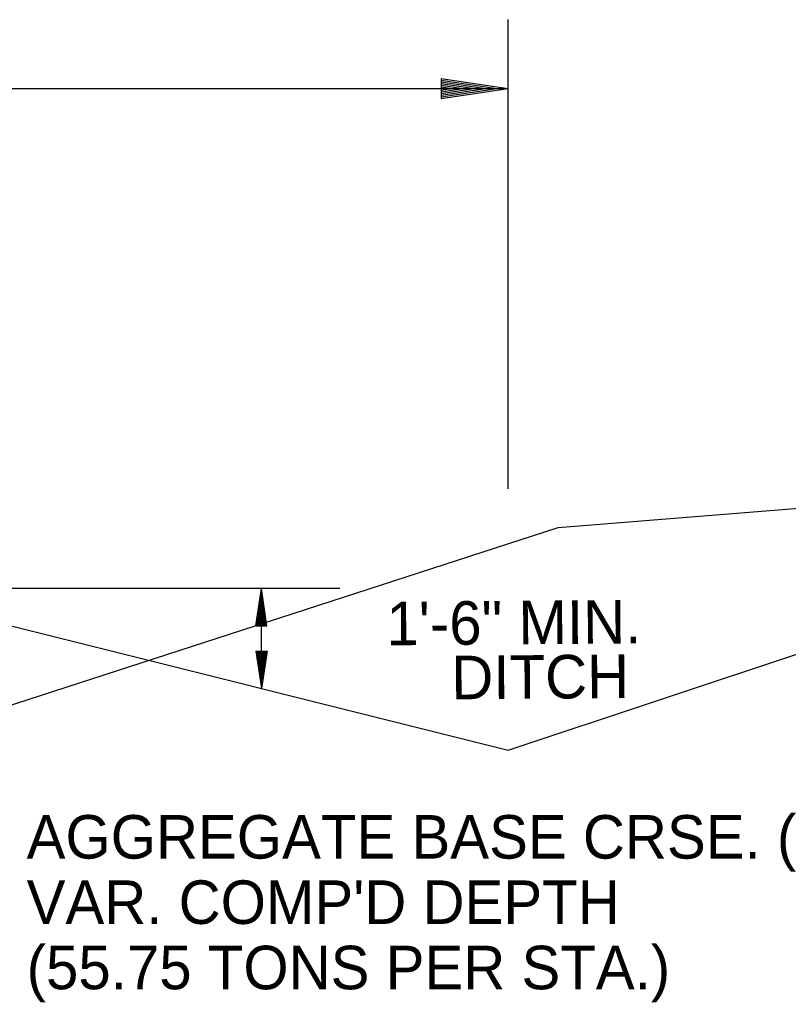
# Model space of a CAD drawing. Extents: x 1373719 to 1374161, y 379835 to 380167.
# Drawn here: x 1373988.41 to 1373999.9, y 380052.46 to 380067.13 of the extents above; entities that cross this region are included whole.
import ezdxf

# ---------------------------------------------------------------- set-up
doc = ezdxf.new("R2010")
doc.units = 0
for name, color, linetype in [('Agg Base Course Text', 7, 'Continuous'), ('Ditch Text - off', 7, 'Continuous'), ('GREEN_TXT', 7, 'Continuous'), ('T_Drafting', 7, 'Continuous')]:
    doc.layers.add(name, color=color, linetype=linetype)

msp = doc.modelspace()

# ---------------------------------------------------------------- linework, layer by layer
for p, q in [((1373995.71, 380056.225), (1374008.612, 380060.525)), ((1373979.707, 380060.226), (1373995.71, 380056.225))]:
    msp.add_line(p, q)
at = {"layer": 'Ditch Text - off'}
for p, q in [((1373986.027, 380058.646), (1373993.195, 380058.646)), ((1373991.941, 380058.084), (1373992.025, 380058.642)), ((1373991.955, 380058.084), (1373992.025, 380058.549)), ((1373992.109, 380058.084), (1373992.025, 380058.642)), ((1373992.095, 380058.084), (1373992.025, 380058.549)), ((1373992.027, 380057.146), (1373992.027, 380058.646)), ((1373991.969, 380058.084), (1373992.025, 380058.453)), ((1373991.983, 380058.084), (1373992.025, 380058.36)), ((1373992.08, 380058.084), (1373992.025, 380058.453)), ((1373992.067, 380058.084), (1373992.025, 380058.36)), ((1373991.998, 380058.084), (1373992.025, 380058.265)), ((1373992.052, 380058.084), (1373992.025, 380058.265)), ((1373991.941, 380058.084), (1373992.109, 380058.084)), ((1373992.012, 380058.084), (1373992.025, 380058.172)), ((1373992.038, 380058.084), (1373992.025, 380058.172)), ((1373991.944, 380057.704), (1373992.027, 380057.146)), ((1373991.944, 380057.704), (1373992.111, 380057.704)), ((1373991.958, 380057.704), (1373992.027, 380057.239)), ((1373991.972, 380057.704), (1373992.027, 380057.335)), ((1373991.986, 380057.704), (1373992.027, 380057.428)), ((1373992, 380057.704), (1373992.027, 380057.523)), ((1373992.014, 380057.704), (1373992.027, 380057.616)), ((1373992.111, 380057.704), (1373992.027, 380057.146)), ((1373992.055, 380057.704), (1373992.027, 380057.523)), ((1373992.083, 380057.704), (1373992.027, 380057.335)), ((1373992.097, 380057.704), (1373992.027, 380057.239)), ((1373992.069, 380057.704), (1373992.027, 380057.428)), ((1373992.041, 380057.704), (1373992.027, 380057.616))]:
    msp.add_line(p, q, dxfattribs=at)
at = {"layer": 'GREEN_TXT'}
for p, q in [((1373995.71, 380060.128), (1373995.71, 380067.13)), ((1373994.71, 380066.253), (1373995.71, 380066.103)), ((1373994.71, 380066.253), (1373994.71, 380065.953)), ((1373994.71, 380066.228), (1373995.543, 380066.103)), ((1373994.71, 380066.203), (1373995.371, 380066.103)), ((1373994.71, 380066.178), (1373995.204, 380066.103)), ((1373994.71, 380066.152), (1373995.035, 380066.103)), ((1373975.718, 380066.104), (1373995.71, 380066.104)), ((1373994.71, 380066.127), (1373994.868, 380066.103)), ((1373994.71, 380065.953), (1373995.71, 380066.103)), ((1373994.71, 380066.054), (1373995.035, 380066.103)), ((1373994.71, 380066.004), (1373995.371, 380066.103)), ((1373994.71, 380065.978), (1373995.543, 380066.103)), ((1373994.71, 380066.029), (1373995.204, 380066.103)), ((1373994.71, 380066.08), (1373994.868, 380066.103))]:
    msp.add_line(p, q, dxfattribs=at)
at = {"layer": 'T_Drafting'}
msp.add_lwpolyline([(1373907.681, 380053.139), (1373924.228, 380053.063), (1373943.144, 380055.229), (1373951.911, 380058.525), (1373953.6, 380058.693), (1373964.739, 380058.703), (1373975.617, 380058.451), (1373977.355, 380058.293), (1373984.395, 380055.639), (1373996.459, 380059.551), (1374008.612, 380060.525), (1374021.604, 380060.525)], dxfattribs=at)

# ---------------------------------------------------------------- texts
at = {"layer": 'Agg Base Course Text'}
for s, p in [('AGGREGATE BASE CRSE. (CL. 7)', (1373988.519, 380054.608)), ("VAR. COMP'D DEPTH", (1373988.519, 380053.633)), ('(55.75 TONS PER STA.)', (1373988.519, 380052.658))]:
    msp.add_text(s, height=0.65, dxfattribs=at).set_placement(p)
at = {"layer": 'Ditch Text - off'}
for s, p in [('1\'-6" MIN.', (1373993.895, 380057.791)), ('DITCH', (1373994.864, 380056.985))]:
    msp.add_text(s, height=0.65, rotation=0.4545, dxfattribs=at).set_placement(p)

doc.saveas('drawing.dxf')
